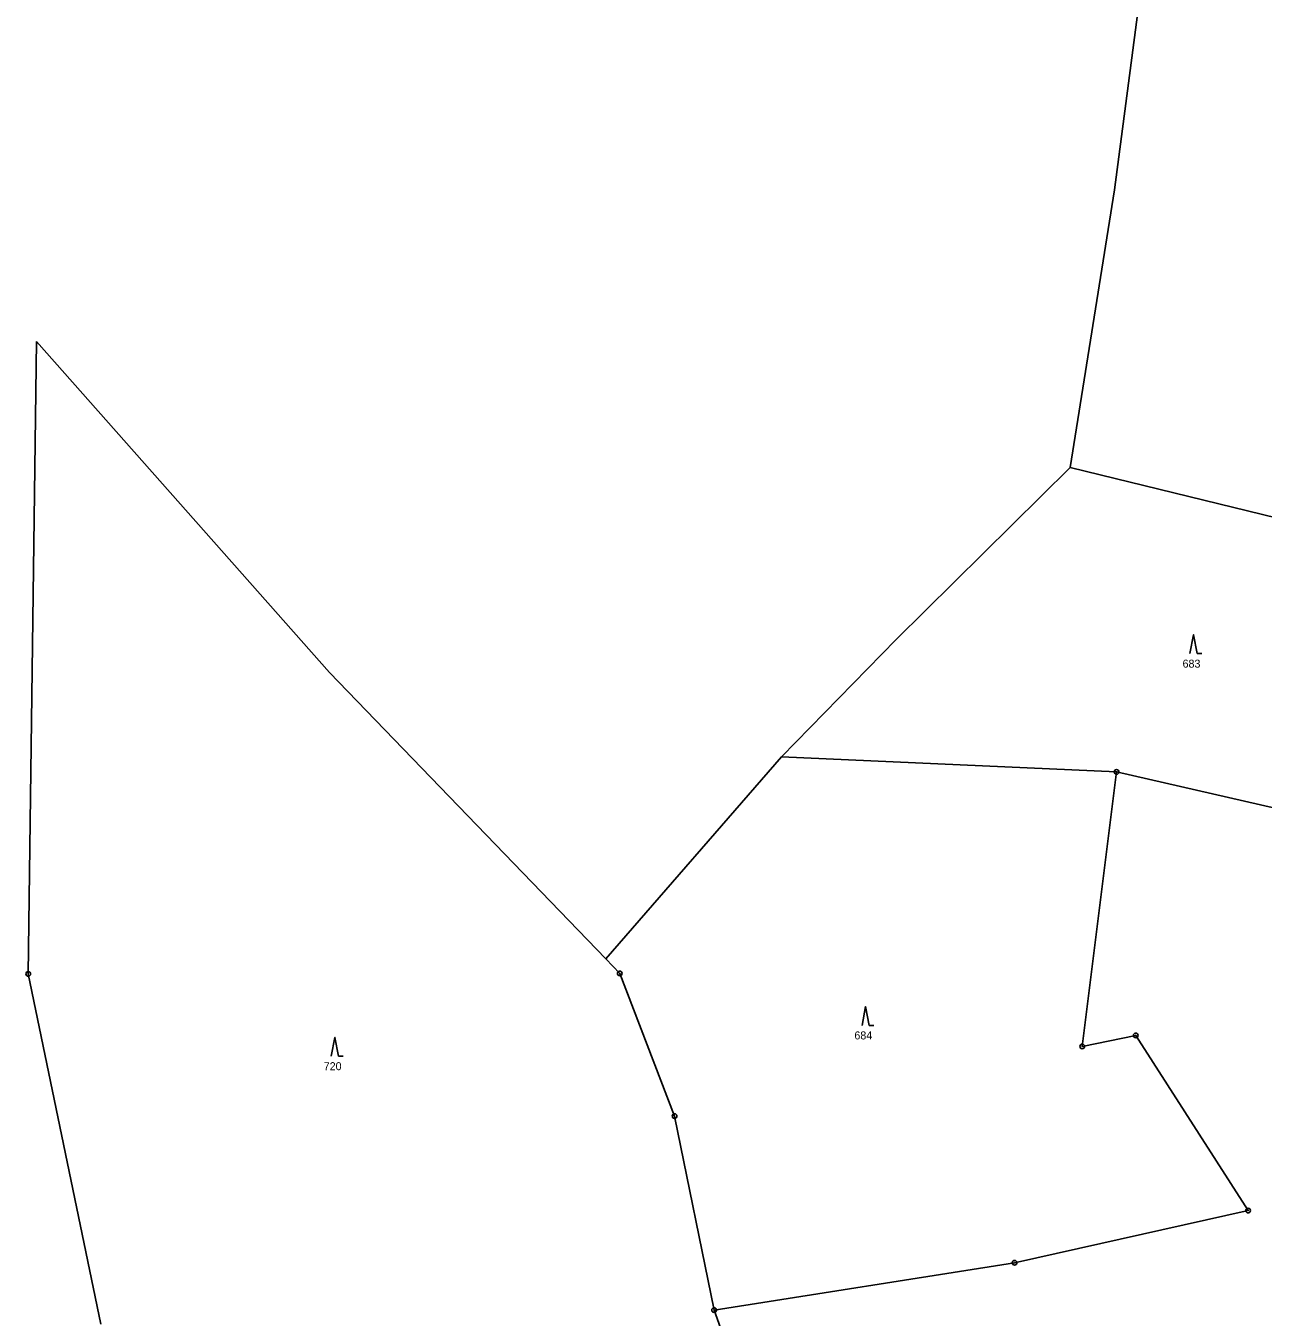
# Model space of a CAD drawing. Extents: x -719614 to -717765, y -1095834 to -1093862.
# Drawn here: x -719567.3 to -719304.3, y -1094975.7 to -1094701.4 of the extents above; entities that cross this region are included whole.
import ezdxf
from ezdxf.enums import TextEntityAlignment as Align

# ---------------------------------------------------------------- set-up
doc = ezdxf.new("R2010")
doc.units = 0
doc.header["$LTSCALE"] = 0.68
for name, color, linetype, lineweight in [('1', 7, 'Continuous', 25), ('3', 7, 'Continuous', 25), ('8', 7, 'Continuous', 25)]:
    doc.layers.add(name, color=color, linetype=linetype, lineweight=lineweight)
doc.layers.add('2', color=7, linetype='Continuous')

msp = doc.modelspace()

# ---------------------------------------------------------------- linework, layer by layer
at = {"layer": '1'}
for p, q in [((-719328.41, -1094678.93), (-719335.91, -1094736.24)), ((-719335.91, -1094736.24), (-719345.39, -1094795.22)), ((-719565.03, -1094768.44), (-719566.79, -1094902.81)), ((-719565.03, -1094768.44), (-719502.78, -1094838.77)), ((-719345.39, -1094795.22), (-719382.34, -1094831.74)), ((-719345.39, -1094795.22), (-719277.58, -1094811.75)), ((-719406.71, -1094856.66), (-719382.34, -1094831.74)), ((-719502.78, -1094838.77), (-719444.01, -1094899.63)), ((-719444.01, -1094899.63), (-719406.71, -1094856.66)), ((-719335.5, -1094859.9), (-719406.71, -1094856.66)), ((-719335.5, -1094859.9), (-719342.81, -1094918.2)), ((-719273.54, -1094874.06), (-719335.5, -1094859.9)), ((-719444.01, -1094899.63), (-719441.06, -1094902.69)), ((-719566.79, -1094902.81), (-719551.36, -1094977.24)), ((-719441.06, -1094902.69), (-719429.44, -1094933)), ((-719342.81, -1094918.2), (-719331.42, -1094915.87)), ((-719331.42, -1094915.87), (-719307.54, -1094953.08)), ((-719429.44, -1094933), (-719421.02, -1094974.23)), ((-719307.54, -1094953.08), (-719357.16, -1094964.17)), ((-719357.16, -1094964.17), (-719421.02, -1094974.23)), ((-719421.02, -1094974.23), (-719415.66, -1094989.06))]:
    msp.add_line(p, q, dxfattribs=at)
at = {"layer": '3'}
for p, q in [((-719318.4, -1094834.75), (-719317.404, -1094834.75)), ((-719388.07, -1094913.74), (-719387.074, -1094913.74)), ((-719500.87, -1094920.28), (-719499.874, -1094920.28))]:
    msp.add_line(p, q, dxfattribs=at)
for points in [[(-719318.4, -1094834.75), (-719319.15, -1094830.75), (-719319.9, -1094834.75)], [(-719388.07, -1094913.74), (-719388.82, -1094909.74), (-719389.57, -1094913.74)], [(-719500.87, -1094920.28), (-719501.62, -1094916.28), (-719502.37, -1094920.28)]]:
    msp.add_lwpolyline(points, dxfattribs=at)
at = {"layer": '8'}
for centre, radius in [((-719335.5, -1094859.8999), 0.5), ((-719335.5, -1094859.8999), 0.0303), ((-719566.79, -1094902.8099), 0.5), ((-719566.79, -1094902.8099), 0.0303), ((-719441.06, -1094902.6899), 0.5), ((-719441.06, -1094902.6899), 0.0303), ((-719331.42, -1094915.8699), 0.5), ((-719331.42, -1094915.8699), 0.0303), ((-719342.81, -1094918.1999), 0.5), ((-719342.81, -1094918.1999), 0.0303), ((-719429.44, -1094932.9999), 0.5), ((-719429.44, -1094932.9999), 0.0303), ((-719307.54, -1094953.0799), 0.5), ((-719307.54, -1094953.0799), 0.0303), ((-719357.16, -1094964.1699), 0.5), ((-719357.16, -1094964.1699), 0.0303), ((-719421.02, -1094974.2299), 0.5), ((-719421.02, -1094974.2299), 0.0303)]:
    msp.add_circle(centre, radius, dxfattribs=at)

# ---------------------------------------------------------------- texts
at = {"layer": '2'}
for s, p in [('683', (-719319.579, -1094837.732)), ('684', (-719389.319, -1094916.722)), ('720', (-719502.089, -1094923.262))]:
    msp.add_text(s, height=1.7, dxfattribs=at).set_placement(p, align=Align.CENTER)

doc.saveas('drawing.dxf')
